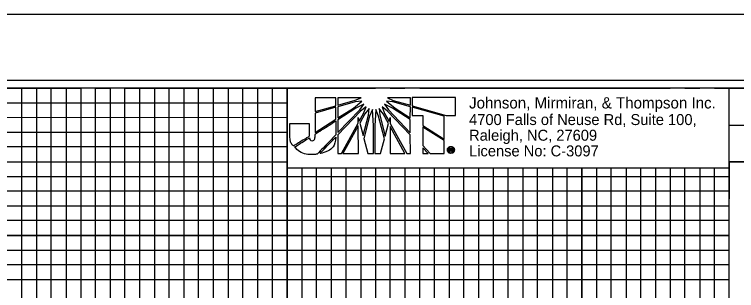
# Model space of a CAD drawing. Extents: x 1648649 to 1651827, y 844691 to 845879.
# Drawn here: x 1651186.8 to 1651431.8, y 845697.3 to 845791 of the extents above; entities that cross this region are included whole.
import ezdxf

# ---------------------------------------------------------------- set-up
doc = ezdxf.new("R2010")
doc.units = 0
for name, color, linetype in [('Prop Dimension Text', 7, 'Continuous'), ('Sheet Cutting Line CELL', 7, 'Continuous'), ('Sheet DOT Grid CELL', 7, 'Continuous'), ('Sheet Plan CELL', 7, 'Continuous'), ('Sheet Plot Border Inside CELL', 7, 'Continuous'), ('Sheet Plot Border Outside CELL', 7, 'Continuous'), ('Sheet Profile CELL', 7, 'Continuous'), ('Sheet Profile Grid Major CELL', 7, 'Continuous'), ('Sheet Profile Grid Middle CELL', 7, 'Continuous'), ('Sheet Profile Grid Minor CELL', 7, 'Continuous')]:
    doc.layers.add(name, color=color, linetype=linetype)

msp = doc.modelspace()

# ---------------------------------------------------------------- linework, layer by layer
at = {"layer": 'Prop Dimension Text'}
for p, q in [((1651295.79, 845762.71), (1651288.77, 845762.7)), ((1651288.77, 845762.7), (1651288.77, 845758.05)), ((1651295.79, 845760), (1651295.79, 845762.71)), ((1651304.41, 845762.75), (1651296.52, 845762.75)), ((1651296.52, 845762.75), (1651296.52, 845760.23)), ((1651302.4, 845761.86), (1651304.41, 845762.75)), ((1651321.14, 845762.73), (1651313.35, 845762.76)), ((1651313.35, 845762.76), (1651315.32, 845761.84)), ((1651321.14, 845760.21), (1651321.14, 845762.73)), ((1651336.43, 845762.78), (1651321.68, 845762.77)), ((1651321.68, 845762.77), (1651321.68, 845760.06)), ((1651336.44, 845756.74), (1651336.43, 845762.78)), ((1651288.77, 845758.05), (1651295.79, 845760)), ((1651296.52, 845760.23), (1651302.4, 845761.86)), ((1651302.4, 845761.31), (1651296.52, 845759.69)), ((1651296.52, 845759.69), (1651296.52, 845755.89)), ((1651301.79, 845759.23), (1651304.69, 845761.59)), ((1651304.69, 845761.59), (1651302.4, 845761.31)), ((1651305.27, 845760.51), (1651302.6, 845759.15)), ((1651303.92, 845758.61), (1651305.27, 845760.51)), ((1651306.08, 845759.66), (1651304.22, 845758.22)), ((1651305.23, 845757.42), (1651306.08, 845759.66)), ((1651311.53, 845759.67), (1651312.39, 845757.42)), ((1651313.39, 845758.23), (1651311.53, 845759.67)), ((1651312.35, 845760.51), (1651313.71, 845758.58)), ((1651315.06, 845759.16), (1651312.35, 845760.51)), ((1651312.96, 845761.6), (1651315.9, 845759.2)), ((1651315.13, 845761.33), (1651312.96, 845761.6)), ((1651321.14, 845759.68), (1651315.13, 845761.33)), ((1651315.32, 845761.84), (1651321.14, 845760.21)), ((1651321.1, 845755.96), (1651321.14, 845759.68)), ((1651321.68, 845760.06), (1651321.68, 845759.98)), ((1651321.68, 845759.98), (1651333.3, 845756.74)), ((1651295.79, 845759.49), (1651288.77, 845757.52)), ((1651288.77, 845757.52), (1651288.78, 845750.97)), ((1651295.79, 845755.43), (1651295.79, 845759.49)), ((1651296.52, 845755.89), (1651301.79, 845759.23)), ((1651302.6, 845759.15), (1651296.52, 845755.28)), ((1651296.53, 845750.9), (1651303.92, 845758.61)), ((1651304.22, 845758.22), (1651296.53, 845750.16)), ((1651303.76, 845754.74), (1651305.23, 845757.42)), ((1651305.7, 845757.25), (1651303.96, 845754.08)), ((1651307.09, 845759.04), (1651305.7, 845757.25)), ((1651306.9, 845756.87), (1651307.09, 845759.04)), ((1651308.25, 845758.73), (1651307.29, 845756.48)), ((1651308.56, 845753.19), (1651308.25, 845758.73)), ((1651309.41, 845758.73), (1651309.05, 845753.19)), ((1651310.34, 845756.48), (1651309.41, 845758.73)), ((1651310.53, 845759.04), (1651310.77, 845756.8)), ((1651311.89, 845757.26), (1651310.53, 845759.04)), ((1651313.71, 845753.97), (1651311.89, 845757.26)), ((1651312.39, 845757.42), (1651313.89, 845754.63)), ((1651321.1, 845750.11), (1651313.39, 845758.23)), ((1651313.71, 845758.58), (1651321.1, 845750.84)), ((1651321.1, 845755.33), (1651315.06, 845759.16)), ((1651315.9, 845759.2), (1651321.1, 845755.96)), ((1651321.68, 845759.56), (1651321.68, 845759.52)), ((1651332.56, 845756.47), (1651321.68, 845759.56)), ((1651321.68, 845759.52), (1651321.69, 845756.69)), ((1651288.78, 845750.97), (1651295.79, 845755.43)), ((1651296.52, 845755.28), (1651296.53, 845750.9)), ((1651303.41, 845754.16), (1651303.41, 845756.01)), ((1651303.41, 845756.01), (1651303.76, 845754.74)), ((1651305.09, 845749.87), (1651306.9, 845756.87)), ((1651307.29, 845756.48), (1651305.32, 845748.89)), ((1651312.36, 845748.78), (1651310.34, 845756.48)), ((1651310.77, 845756.8), (1651312.59, 845749.71)), ((1651313.89, 845754.63), (1651314.25, 845756.02)), ((1651314.25, 845756.02), (1651314.25, 845753.97)), ((1651321.1, 845750.84), (1651321.1, 845755.33)), ((1651321.69, 845756.69), (1651325.29, 845756.69)), ((1651325.29, 845756.69), (1651325.29, 845753.32)), ((1651332.57, 845748.72), (1651332.56, 845756.47)), ((1651333.3, 845756.74), (1651336.44, 845756.74)), ((1651297.69, 845743.79), (1651303.41, 845754.16)), ((1651303.42, 845753.15), (1651298.24, 845743.79)), ((1651303.47, 845743.8), (1651303.42, 845753.15)), ((1651303.96, 845754.08), (1651305.09, 845749.87)), ((1651308.57, 845743.84), (1651308.56, 845753.19)), ((1651309.05, 845753.19), (1651309.06, 845743.84)), ((1651312.59, 845749.71), (1651313.71, 845753.97)), ((1651314.25, 845753.97), (1651319.87, 845743.81)), ((1651319.29, 845743.85), (1651314.25, 845752.97)), ((1651314.25, 845752.97), (1651314.26, 845743.84)), ((1651325.29, 845753.32), (1651332.57, 845748.72)), ((1651325.29, 845752.74), (1651325.3, 845746.47)), ((1651332.57, 845748.18), (1651325.29, 845752.74)), ((1651296.53, 845750.16), (1651296.53, 845743.79)), ((1651321.11, 845743.81), (1651321.1, 845750.11)), ((1651305.32, 845748.89), (1651306.64, 845743.83)), ((1651311.01, 845743.84), (1651312.36, 845748.78)), ((1651332.57, 845743.82), (1651332.57, 845748.18)), ((1651325.3, 845746.47), (1651327.81, 845743.82)), ((1651327.12, 845743.82), (1651325.3, 845745.78)), ((1651325.3, 845745.78), (1651325.3, 845743.82)), ((1651334.42, 845744.49), (1651334.42, 845745.56)), ((1651334.42, 845745.56), (1651334.86, 845745.56)), ((1651334.86, 845745.36), (1651334.66, 845745.36)), ((1651334.66, 845745.36), (1651334.66, 845745.1)), ((1651334.66, 845745.1), (1651334.86, 845745.1)), ((1651334.86, 845744.91), (1651334.66, 845744.91)), ((1651334.66, 845744.91), (1651334.66, 845744.49)), ((1651334.86, 845746.19), (1651334.86, 845745.97)), ((1651334.86, 845745.97), (1651334.86, 845746.19)), ((1651334.86, 845745.56), (1651334.86, 845745.36)), ((1651334.86, 845745.36), (1651334.86, 845745.56)), ((1651334.86, 845745.56), (1651334.92, 845745.56)), ((1651334.89, 845745.36), (1651334.86, 845745.36)), ((1651334.86, 845745.1), (1651334.86, 845744.91)), ((1651334.86, 845744.91), (1651334.86, 845745.1)), ((1651334.86, 845745.1), (1651334.87, 845745.1)), ((1651334.87, 845744.91), (1651334.86, 845744.91)), ((1651296.53, 845743.79), (1651297.69, 845743.79)), ((1651298.24, 845743.79), (1651303.47, 845743.8)), ((1651306.64, 845743.83), (1651308.57, 845743.84)), ((1651309.06, 845743.84), (1651311.01, 845743.84)), ((1651314.26, 845743.84), (1651319.29, 845743.85)), ((1651319.87, 845743.81), (1651321.11, 845743.81)), ((1651325.3, 845743.82), (1651327.12, 845743.82)), ((1651327.81, 845743.82), (1651332.57, 845743.82)), ((1651334.66, 845744.49), (1651334.42, 845744.49)), ((1651334.86, 845744.07), (1651334.86, 845743.83)), ((1651334.86, 845743.83), (1651334.86, 845744.07)), ((1651334.86, 845744.07), (1651334.87, 845744.07)), ((1651334.87, 845743.83), (1651334.86, 845743.83))]:
    msp.add_line(p, q, dxfattribs=at)
msp.add_lwpolyline([(1651279.28, 845738.96), (1651429.23, 845738.96), (1651429.23, 845766.02), (1651279.28, 845766.02)], close=True, dxfattribs=at)
for points in [[(1651288.77, 845758.05), (1651295.79, 845760), (1651295.79, 845762.71), (1651288.77, 845762.7), (1651288.77, 845758.05)], [(1651302.4, 845761.86), (1651304.41, 845762.75), (1651296.52, 845762.75), (1651296.52, 845760.23), (1651302.4, 845761.86)], [(1651315.32, 845761.84), (1651321.14, 845760.21), (1651321.14, 845762.73), (1651313.35, 845762.76), (1651315.32, 845761.84)], [(1651336.43, 845762.78), (1651321.68, 845762.77), (1651321.68, 845760.06), (1651321.68, 845759.98), (1651333.3, 845756.74), (1651336.44, 845756.74), (1651336.43, 845762.78)], [(1651296.52, 845759.69), (1651296.52, 845755.89), (1651301.79, 845759.23), (1651304.69, 845761.59), (1651302.4, 845761.31), (1651296.52, 845759.69)], [(1651296.52, 845755.28), (1651296.53, 845750.9), (1651303.92, 845758.61), (1651305.27, 845760.51), (1651302.6, 845759.15), (1651296.52, 845755.28)], [(1651306.08, 845759.66), (1651304.22, 845758.22), (1651296.53, 845750.16), (1651296.53, 845743.79), (1651297.69, 845743.79), (1651303.41, 845754.16), (1651303.41, 845756.01), (1651303.76, 845754.74), (1651305.23, 845757.42), (1651306.08, 845759.66)], [(1651311.53, 845759.67), (1651312.39, 845757.42), (1651313.89, 845754.63), (1651314.25, 845756.02), (1651314.25, 845753.97), (1651319.87, 845743.81), (1651321.11, 845743.81), (1651321.1, 845750.11), (1651313.39, 845758.23), (1651311.53, 845759.67)], [(1651312.35, 845760.51), (1651313.71, 845758.58), (1651321.1, 845750.84), (1651321.1, 845755.33), (1651315.06, 845759.16), (1651312.35, 845760.51)], [(1651312.96, 845761.6), (1651315.9, 845759.2), (1651321.1, 845755.96), (1651321.14, 845759.68), (1651315.13, 845761.33), (1651312.96, 845761.6)], [(1651288.78, 845750.97), (1651295.79, 845755.43), (1651295.79, 845759.49), (1651288.77, 845757.52), (1651288.78, 845750.97)], [(1651307.09, 845759.04), (1651305.7, 845757.25), (1651303.96, 845754.08), (1651305.09, 845749.87), (1651306.9, 845756.87), (1651307.09, 845759.04)], [(1651307.29, 845756.48), (1651305.32, 845748.89), (1651306.64, 845743.83), (1651308.57, 845743.84), (1651308.56, 845753.19), (1651308.25, 845758.73), (1651307.29, 845756.48)], [(1651309.41, 845758.73), (1651309.05, 845753.19), (1651309.06, 845743.84), (1651311.01, 845743.84), (1651312.36, 845748.78), (1651310.34, 845756.48), (1651309.41, 845758.73)], [(1651310.53, 845759.04), (1651310.77, 845756.8), (1651312.59, 845749.71), (1651313.71, 845753.97), (1651311.89, 845757.26), (1651310.53, 845759.04)], [(1651321.68, 845759.56), (1651321.68, 845759.52), (1651321.69, 845756.69), (1651325.29, 845756.69), (1651325.29, 845753.32), (1651332.57, 845748.72), (1651332.56, 845756.47), (1651321.68, 845759.56)], [(1651298.24, 845743.79), (1651303.47, 845743.8), (1651303.42, 845753.15), (1651298.24, 845743.79)], [(1651314.26, 845743.84), (1651319.29, 845743.85), (1651314.25, 845752.97), (1651314.26, 845743.84)], [(1651325.29, 845752.74), (1651325.3, 845746.47), (1651327.81, 845743.82), (1651332.57, 845743.82), (1651332.57, 845748.18), (1651325.29, 845752.74), (1651325.29, 845752.74)], [(1651325.3, 845743.82), (1651325.3, 845743.82), (1651327.12, 845743.82), (1651325.3, 845745.78), (1651325.3, 845743.82)], [(1651335.33, 845744.74), (1651335.33, 845744.68), (1651335.33, 845744.64), (1651335.33, 845744.61), (1651335.36, 845744.49), (1651335.14, 845744.49)]]:
    msp.add_lwpolyline(points, dxfattribs=at)
for points, degree in [([(1651287.78, 845748.13), (1651287.36, 845748.13), (1651287, 845748.37), (1651286.85, 845749.14), (1651286.85, 845749.14), (1651281.81, 845746.02), (1651281.81, 845746.02), (1651283.37, 845744.39), (1651285.85, 845743.42), (1651287.94, 845743.42), (1651288.49, 845743.42), (1651288.9, 845743.47), (1651289.48, 845743.59), (1651289.48, 845743.59), (1651295.8, 845750.12), (1651295.8, 845750.12), (1651295.8, 845750.12), (1651295.79, 845754.85), (1651295.79, 845754.85), (1651295.79, 845754.85), (1651288.78, 845750.38), (1651288.78, 845750.38), (1651288.78, 845748.61), (1651288.35, 845748.14), (1651287.78, 845748.13)], 3), ([(1651287.78, 845748.13), (1651287.36, 845748.13), (1651287, 845748.37), (1651286.85, 845749.14), (1651286.85, 845749.14), (1651281.81, 845746.02), (1651281.81, 845746.02), (1651283.37, 845744.39), (1651285.85, 845743.42), (1651287.94, 845743.42), (1651288.49, 845743.42), (1651288.9, 845743.47), (1651289.48, 845743.59), (1651289.48, 845743.59), (1651295.8, 845750.12), (1651295.8, 845750.12), (1651295.8, 845750.12), (1651295.79, 845754.85), (1651295.79, 845754.85), (1651295.79, 845754.85), (1651288.78, 845750.38), (1651288.78, 845750.38), (1651288.78, 845748.61), (1651288.35, 845748.14), (1651287.78, 845748.13)], 3), ([(1651286.76, 845753.98), (1651286.76, 845753.98), (1651280.27, 845753.98), (1651280.27, 845753.98), (1651280.27, 845753.98), (1651280.27, 845749.91), (1651280.27, 845749.91), (1651280.27, 845749.91), (1651280.27, 845749.48), (1651280.27, 845749.48), (1651280.27, 845748.21), (1651280.69, 845747.2), (1651281.43, 845746.36), (1651281.43, 845746.36), (1651286.77, 845749.6), (1651286.77, 845749.69), (1651286.77, 845749.69), (1651286.76, 845753.98), (1651286.76, 845753.98)], 3), ([(1651295.8, 845749.38), (1651295.8, 845749.38), (1651290.34, 845743.74), (1651290.34, 845743.74), (1651293.01, 845744.4), (1651295.68, 845746.17), (1651295.8, 845749.38)], 3), ([(1651334.86, 845743.83), (1651334.54, 845743.83), (1651334.25, 845743.95), (1651334.02, 845744.18), (1651333.78, 845744.41), (1651333.67, 845744.69), (1651333.67, 845745.02), (1651333.67, 845745.35), (1651333.78, 845745.64), (1651334.02, 845745.85), (1651334.25, 845746.08), (1651334.52, 845746.19), (1651334.86, 845746.19)], 3), ([(1651334.86, 845745.97), (1651334.59, 845745.97), (1651334.37, 845745.88), (1651334.18, 845745.71), (1651334, 845745.52), (1651333.9, 845745.29), (1651333.9, 845745.02), (1651333.9, 845744.76), (1651334, 845744.53), (1651334.18, 845744.34), (1651334.37, 845744.16), (1651334.59, 845744.07), (1651334.86, 845744.07)], 3), ([(1651334.86, 845746.19), (1651335.19, 845746.19), (1651335.47, 845746.08), (1651335.7, 845745.85), (1651335.94, 845745.64), (1651336.06, 845745.36), (1651336.06, 845745.03)], 3), ([(1651334.87, 845744.07), (1651335.13, 845744.07), (1651335.35, 845744.16), (1651335.54, 845744.34), (1651335.72, 845744.53), (1651335.82, 845744.76), (1651335.82, 845745.03), (1651335.82, 845745.29), (1651335.72, 845745.52), (1651335.54, 845745.71), (1651335.35, 845745.88), (1651335.13, 845745.97), (1651334.86, 845745.97)], 3), ([(1651334.87, 845745.1), (1651335.02, 845745.1), (1651335.1, 845745.15), (1651335.1, 845745.24), (1651335.1, 845745.32), (1651335.03, 845745.36), (1651334.89, 845745.36)], 3), ([(1651336.06, 845745.03), (1651336.06, 845744.69), (1651335.94, 845744.41), (1651335.72, 845744.18), (1651335.48, 845743.95), (1651335.2, 845743.83), (1651334.87, 845743.83)], 3), ([(1651335.05, 845744.87), (1651335.02, 845744.89), (1651334.96, 845744.91), (1651334.87, 845744.91)], 2), ([(1651334.92, 845745.56), (1651335.2, 845745.56), (1651335.33, 845745.45), (1651335.33, 845745.24), (1651335.33, 845745.14), (1651335.3, 845745.06), (1651335.21, 845745)], 3), ([(1651335.21, 845745), (1651335.28, 845744.97), (1651335.32, 845744.88), (1651335.33, 845744.74)], 2), ([(1651335.14, 845744.49), (1651335.11, 845744.55), (1651335.09, 845744.61), (1651335.09, 845744.68), (1651335.09, 845744.78), (1651335.08, 845744.84), (1651335.05, 845744.87)], 3)]:
    msp.add_open_spline(points, degree=degree, dxfattribs=at)
at = {"layer": 'Sheet Cutting Line CELL'}
msp.add_line((1651646.28, 845791.02), (1649962.28, 845791.02), dxfattribs=at)
at = {"layer": 'Sheet DOT Grid CELL'}
for p, q in [((1651229.28, 845266.02), (1651229.28, 845766.02)), ((1651279.28, 845266.02), (1651279.28, 845766.02)), ((1651329.28, 845266.02), (1651329.28, 845738.96)), ((1651379.28, 845266.02), (1651379.28, 845738.96)), ((1651229.28, 845266.02), (1651229.28, 845718.48)), ((1651329.28, 845266.02), (1651329.28, 845718.48)), ((1651379.28, 845266.02), (1651379.28, 845718.48)), ((1651429.23, 845716.02), (1650129.28, 845716.02)), ((1651429.23, 845716.02), (1650129.28, 845716.02)), ((1651279.28, 845266.02), (1651279.28, 845716.02))]:
    msp.add_line(p, q, dxfattribs=at)
at = {"layer": 'Sheet Plan CELL'}
msp.add_line((1651429.23, 845740.94), (1651429.23, 845728.45), dxfattribs=at)
msp.add_line((1651429.23, 845740.94), (1651429.23, 845728.45), dxfattribs=at)
at = {"layer": 'Sheet Plot Border Inside CELL'}
msp.add_lwpolyline([(1649975.28, 844713.47), (1651641.78, 844713.47), (1651641.78, 845768.57), (1649975.28, 845768.57)], close=True, dxfattribs=at)
at = {"layer": 'Sheet Plot Border Outside CELL'}
msp.add_lwpolyline([(1649962.28, 844691.02), (1651646.28, 844691.02), (1651646.28, 845791.02), (1649962.28, 845791.02)], close=True, dxfattribs=at)
at = {"layer": 'Sheet Profile CELL'}
msp.add_line((1651429.23, 845753.47), (1651629.28, 845753.47), dxfattribs=at)
for points in [[(1651629.28, 845766.02), (1650129.28, 845766.02), (1650129.28, 844716.02), (1651629.28, 844716.02)], [(1651429.23, 845766.02), (1651629.28, 845766.02), (1651629.28, 845740.97), (1651429.23, 845740.97)], [(1651429.23, 845740.97), (1651529.28, 845740.97), (1651529.28, 845628.47), (1651429.23, 845628.47)]]:
    msp.add_lwpolyline(points, close=True, dxfattribs=at)
at = {"layer": 'Sheet Profile Grid Major CELL'}
for points in [[(1650879.28, 845266.02), (1650929.28, 845266.02), (1650929.28, 845766.02), (1650979.28, 845766.02), (1650979.28, 845266.02), (1651029.28, 845266.02), (1651029.28, 845766.02), (1651079.28, 845766.02), (1651079.28, 845266.02), (1651129.28, 845266.02), (1651129.28, 845766.02), (1651179.28, 845766.02), (1651179.28, 845266.02), (1651229.28, 845266.02), (1651229.28, 845766.02), (1651279.28, 845766.02), (1651279.28, 845266.02), (1651329.28, 845266.02), (1651329.28, 845738.96)], [(1651329.28, 845766.02), (1651379.28, 845766.02)], [(1651379.28, 845738.96), (1651379.28, 845266.02), (1651429.28, 845266.02), (1651429.28, 845766.02), (1651455.58, 845766.02)], [(1650129.28, 845716.02), (1651429.28, 845716.02)]]:
    msp.add_lwpolyline(points, dxfattribs=at)
at = {"layer": 'Sheet Profile Grid Middle CELL'}
msp.add_line((1650129.28, 845741.02), (1651279.28, 845741.02), dxfattribs=at)
for points in [[(1650904.28, 845266.02), (1650954.28, 845266.02), (1650954.28, 845766.02), (1651004.28, 845766.02), (1651004.28, 845266.02), (1651054.28, 845266.02), (1651054.28, 845766.02), (1651104.28, 845766.02), (1651104.28, 845266.02), (1651154.28, 845266.02), (1651154.28, 845766.02), (1651204.28, 845766.02), (1651204.28, 845266.02), (1651254.28, 845266.02), (1651254.28, 845766.02), (1651304.28, 845766.02)], [(1651354.28, 845766.02), (1651404.28, 845766.02)], [(1651304.28, 845738.96), (1651304.28, 845266.02), (1651354.28, 845266.02), (1651354.28, 845738.96)], [(1651404.28, 845738.96), (1651404.28, 845266.02), (1651454.28, 845266.02), (1651454.28, 845604.97)]]:
    msp.add_lwpolyline(points, dxfattribs=at)
at = {"layer": 'Sheet Profile Grid Minor CELL'}
for p, q in [((1650179.28, 845761.02), (1651279.28, 845761.02)), ((1651429.23, 845761.02), (1651429.28, 845761.02)), ((1651279.28, 845755.98), (1650179.28, 845755.67)), ((1651429.28, 845756.02), (1651429.23, 845756.02)), ((1650179.28, 845751.02), (1651279.28, 845751.02)), ((1651429.23, 845751.02), (1651429.28, 845751.02))]:
    msp.add_line(p, q, dxfattribs=at)
for points in [[(1651189.28, 845266.02), (1651189.28, 845766.02), (1651194.28, 845766.02), (1651194.28, 845266.02)], [(1651199.28, 845266.02), (1651199.28, 845766.02), (1651209.28, 845766.02), (1651209.28, 845266.02)], [(1651214.28, 845266.02), (1651214.28, 845766.02), (1651219.28, 845766.02), (1651219.28, 845266.02)], [(1651224.28, 845266.02), (1651224.28, 845766.02), (1651234.28, 845766.02), (1651234.28, 845266.02)], [(1651239.28, 845266.02), (1651239.28, 845766.02), (1651244.28, 845766.02), (1651244.28, 845266.02)], [(1651249.28, 845266.02), (1651249.28, 845766.02), (1651259.28, 845766.02), (1651259.28, 845266.02)], [(1651264.28, 845266.02), (1651264.28, 845766.02), (1651269.28, 845766.02), (1651269.28, 845266.02)], [(1651274.28, 845266.02), (1651274.28, 845766.02), (1651284.28, 845766.02)], [(1651289.28, 845766.02), (1651294.28, 845766.02)], [(1651299.28, 845766.02), (1651309.28, 845766.02)], [(1651314.28, 845766.02), (1651319.28, 845766.02)], [(1651324.28, 845766.02), (1651334.28, 845766.02)], [(1651339.28, 845766.02), (1651344.28, 845766.02)], [(1651349.28, 845766.02), (1651359.28, 845766.02)], [(1651364.28, 845766.02), (1651369.28, 845766.02)], [(1651374.28, 845766.02), (1651384.28, 845766.02)], [(1651389.28, 845766.02), (1651394.28, 845766.02)], [(1651399.28, 845766.02), (1651409.28, 845766.02)], [(1651414.28, 845766.02), (1651419.28, 845766.02)], [(1651424.28, 845766.02), (1651434.28, 845766.02)], [(1651279.28, 845746.02), (1650179.28, 845746.02), (1650179.28, 845736.02), (1651429.28, 845736.02)], [(1651429.28, 845746.02), (1651429.23, 845746.02)], [(1651284.28, 845738.96), (1651284.28, 845266.02), (1651289.28, 845266.02), (1651289.28, 845738.96)], [(1651294.28, 845738.96), (1651294.28, 845266.02), (1651299.28, 845266.02), (1651299.28, 845738.96)], [(1651309.28, 845738.96), (1651309.28, 845266.02), (1651314.28, 845266.02), (1651314.28, 845738.96)], [(1651319.28, 845266.02), (1651324.28, 845266.02), (1651324.28, 845738.96)], [(1651319.28, 845738.96), (1651319.28, 845266.02)], [(1651334.28, 845738.96), (1651334.28, 845266.02), (1651339.28, 845266.02), (1651339.28, 845738.96)], [(1651344.28, 845738.96), (1651344.28, 845266.02), (1651349.28, 845266.02), (1651349.28, 845738.96)], [(1651359.28, 845738.96), (1651359.28, 845266.02), (1651364.28, 845266.02), (1651364.28, 845738.96)], [(1651369.28, 845738.96), (1651369.28, 845266.02), (1651374.28, 845266.02), (1651374.28, 845738.96)], [(1651384.28, 845738.96), (1651384.28, 845266.02), (1651389.28, 845266.02), (1651389.28, 845738.96)], [(1651394.28, 845738.96), (1651394.28, 845266.02), (1651399.28, 845266.02), (1651399.28, 845738.96)], [(1651409.28, 845738.96), (1651409.28, 845266.02), (1651414.28, 845266.02), (1651414.28, 845738.96)], [(1651419.28, 845738.96), (1651419.28, 845266.02), (1651424.28, 845266.02), (1651424.28, 845738.96)], [(1651429.23, 845731.02), (1650179.28, 845731.02), (1650179.28, 845726.02), (1651429.28, 845726.02)], [(1651429.28, 845721.02), (1650179.28, 845721.02), (1650179.28, 845711.02), (1651429.28, 845711.02)], [(1651429.28, 845706.02), (1650179.28, 845706.02), (1650179.28, 845701.02), (1651429.28, 845701.02)]]:
    msp.add_lwpolyline(points, dxfattribs=at)

# ---------------------------------------------------------------- texts
at = {"layer": 'Prop Dimension Text'}
for s, height, p in [('Johnson, Mirmiran, & Thompson Inc.', 3.8315, (1651341.03, 845759.09)), ('4700 Falls of Neuse Rd, Suite 100, ', 3.722, (1651341.03, 845753.47)), ('Raleigh, NC, 27609', 3.722, (1651341.03, 845748.15)), ('License No: C-3097', 3.722, (1651341.03, 845742.83))]:
    msp.add_text(s, height=height, rotation=360, dxfattribs=at).set_placement(p)

doc.saveas('drawing.dxf')
